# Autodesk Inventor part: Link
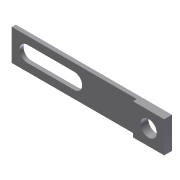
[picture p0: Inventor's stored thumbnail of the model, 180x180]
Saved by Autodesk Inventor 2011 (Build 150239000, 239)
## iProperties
Created: 2010-05
Part Number: Link
Document SubType Name: Modeling
Designer: Phil
Density: 1 g/cm^3
Author: Phil
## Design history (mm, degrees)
sketch "Sketch1"
  geometry: L1 (0, 0)-(63.5, 0); L2 (63.5, 0)-(63.5, 12.7); L3 (63.5, 12.7)-(0, 12.7); L4 (0, 12.7)-(0, 0)
  constraints: 8 end point, 2 parallel, 1 horizontal, 1 perpendicular
  dimensions: "d0" = 63.5 distance of L3.end L2.end; "d1" = 12.7 distance of L2.end L1.end
extrude "Extrusion1" new body sketch "Sketch1" distance "d2" = 3.175; taper "d3" = 0 deg
sketch "Sketch2"
  geometry: L1 (0, 0)-(50.8, 0); L2 (50.8, 0)-(50.8, 1.556); L3 (50.8, 1.556)-(0, 1.556); L4 (0, 1.556)-(0, 0)
  constraints: 8 end point, 2 parallel, 1 horizontal, 1 perpendicular
  dimensions: "d4" = 50.8 distance of L3.end L2.end; "d5" = 1.55575 distance of L2.end L1.end
extrude "Extrusion2" cut sketch "Sketch2" stored distance "d6" = 3.175; taper "d7" = 0 deg
sketch "Sketch3"
  geometry: L1 (0, -12.7)-(0, 0) reference; L2 (6.35, -9.507)-(25.4, -9.507); L3 (25.4, -3.107)-(6.35, -3.107); A1 r 3.2 centre (25.4, -6.307) between (25.4, -9.507) and (25.4, -3.107); A2 r 3.2 centre (6.35, -6.307) between (6.35, -3.107) and (6.35, -9.507)
  constraints: 4 end point, 4 point on circle, 4 tangent, 2 centre point, 1 parallel, 1 perpendicular
  dimensions: "d8" = 19.05 distance of A1.centre A2.centre; "d9" = 6.35 distance from line of L1 A2.centre; "d10" = 3.2004 radius of A2
extrude "Extrusion3" cut sketch "Sketch3" stored distance "d11" = 3.175; taper "d12" = 0 deg
sketch "Sketch4"
  geometry: L1 (63.5, 0)-(63.5, 12.7) reference; 3 further points
  constraints: 1 horizontal alignment, 1 midpoint
  dimensions: "d13" = 6.35 distance from line of L1 point (57.15, 6.35)
hole "Hole1" sketch "Sketch4" at (57.15, 6.35) diameter "d14" = 6.604; stored, may be unused: countersink angle "d18" = 82 deg, drill point angle "d20" = 118 deg; dims "d15" = 19.05, "d16" = 9.525, "d17" = 6.35, "d19" = 25.4
body "Solid1"
